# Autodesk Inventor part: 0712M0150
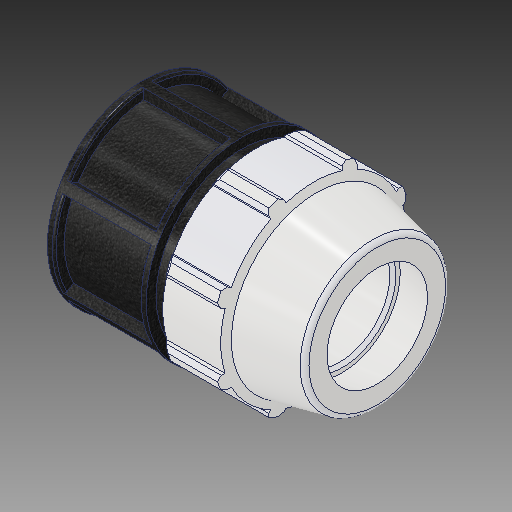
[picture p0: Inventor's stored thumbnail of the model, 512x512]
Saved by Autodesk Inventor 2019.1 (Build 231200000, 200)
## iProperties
Created: 2017-02
Part Number: 0712M0150
Material: PVC-Piping
Description: PLASSON END PLUG 1 1/2''
Document SubType Name: Modeling
Designer: KIM
Mass: 92.6774 g
Surface Area: 199.44 cm^2
Volume: 66.1981 cm^3
Density: 1.4 g/cm^3
Appearance: PTFE
Author: Кирилл
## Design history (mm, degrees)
derived "0712M0.ipt"
feature "Solid1::0712M0.ipt"
tag "TaggingFeature1"
body "Solid1"
other parameters: "d2" = 48.1, "d4" = 16.58257, "d5" = 29.0195, "d7" = 96.012, "d8" = 81.6102, "d9" = 16.58257, "d11" = 3.31651, "d12" = 81.6102, "d13" = 120 deg, "d15" = 12 deg, "d16" = 91.2114, "d18" = 2.405, "d19" = 35 deg, "d20" = 17.5 deg, "d21" = 89.29116, "d23" = 0, "d25" = 360 deg, "d27" = 1.92024, "d34" = 4.8006, "d36" = 0, "d42" = 29.0195, "d43" = 2.88036, "d46" = 1.443, "d53" = 0.962, "d55" = 360 deg, "d59" = 40.6273, "d64" = 116.078, "d66" = 9.6012, "d67" = 4.8006, "d68" = 108.966, "d70" = 81.6102, "d_" = 48.1, "E_" = 96.012, "H_" = 116.078, "l_" = 108.966
